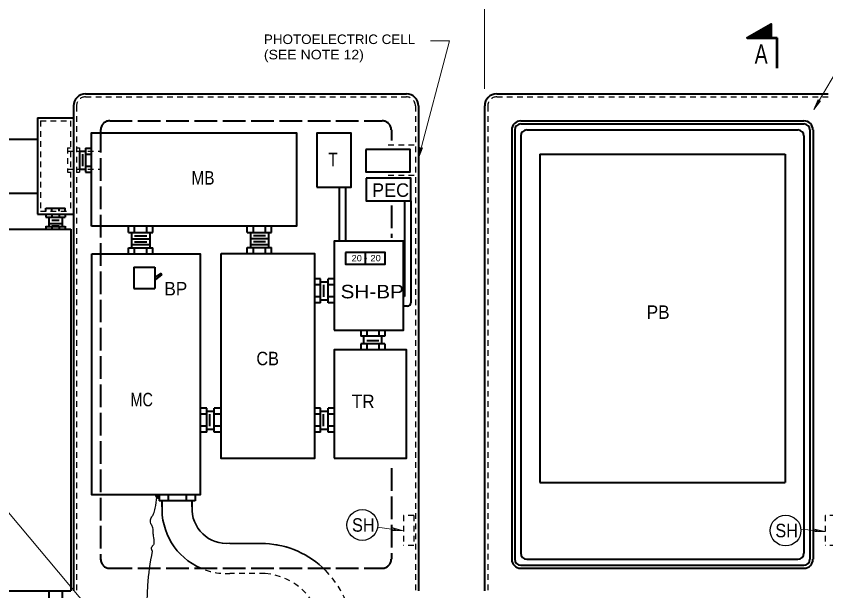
# Model space of a CAD drawing. Extents: x 312583 to 312854, y 144419 to 144597.
# Drawn here: x 312632.5 to 312696.9, y 144527.3 to 144573 of the extents above; entities that cross this region are included whole.
import ezdxf
from ezdxf.enums import TextEntityAlignment as Align

# ---------------------------------------------------------------- set-up
doc = ezdxf.new("R2010")
doc.units = 0
doc.header["$LTSCALE"] = 0.3
doc.header["$PDMODE"] = 32
doc.header["$PDSIZE"] = 0.15
doc.linetypes.add('LONG_DASHED', pattern=[7.5, 6, -1.5])
doc.linetypes.add('SHORT_DASHED', pattern=[2.7, 1.5, -1.2])
doc.layers.add('1', color=7, linetype='Continuous', lineweight=25)
doc.layers.add('2', color=7, linetype='Continuous', lineweight=13)

msp = doc.modelspace()

# ---------------------------------------------------------------- linework, layer by layer
at = {"layer": '1', "lineweight": 35}
for p, q in [((312691.9578, 144571.2646), (312691.6281, 144571.8396)), ((312691.9808, 144571.2646), (312691.6511, 144571.8473)), ((312692.0115, 144571.2646), (312691.6741, 144571.8626)), ((312692.0421, 144571.2646), (312691.6895, 144571.8703)), ((312692.0728, 144571.2646), (312691.7125, 144571.8856)), ((312692.0958, 144571.2646), (312691.7355, 144571.8933)), ((312692.1188, 144571.2646), (312691.7508, 144571.9086)), ((312692.1495, 144571.2723), (312691.7738, 144571.9163)), ((312692.1801, 144571.2646), (312691.7968, 144571.9316)), ((312692.2031, 144571.2646), (312691.8121, 144571.9393)), ((312692.2338, 144571.2646), (312691.8351, 144571.9546)), ((312692.2645, 144571.2646), (312691.8581, 144571.97)), ((312692.2875, 144571.2646), (312691.8811, 144571.9776)), ((312692.3181, 144571.2646), (312691.8965, 144571.993)), ((312692.3488, 144571.2646), (312691.9195, 144572.0083)), ((312692.3718, 144571.2723), (312691.9425, 144572.016)), ((312692.4025, 144571.2723), (312691.9578, 144572.0313)), ((312692.4255, 144571.2646), (312691.9808, 144572.039)), ((312692.4561, 144571.2646), (312692.0038, 144572.0543)), ((312692.4791, 144571.2646), (312692.0191, 144572.062)), ((312692.5098, 144571.2646), (312692.0421, 144572.0773)), ((312692.5405, 144571.2646), (312692.0651, 144572.085)), ((312692.5558, 144571.2876), (312692.0805, 144572.1003)), ((312692.5558, 144571.3413), (312692.1111, 144572.108)), ((312692.5558, 144571.3796), (312692.1265, 144572.1233)), ((312692.5558, 144571.4333), (312692.1495, 144572.131)), ((312692.5558, 144571.4793), (312692.1725, 144572.1463)), ((312692.5558, 144571.5253), (312692.1878, 144572.1616)), ((312692.5558, 144571.5713), (312692.2108, 144572.1693)), ((312692.5558, 144571.625), (312692.2338, 144572.1846)), ((312692.5558, 144571.671), (312692.2491, 144572.2)), ((312692.5558, 144571.717), (312692.2721, 144572.2076)), ((312692.5558, 144571.7706), (312692.2875, 144572.223)), ((312692.5558, 144571.8166), (312692.3105, 144572.2306)), ((312692.5558, 144571.8626), (312692.3335, 144572.246)), ((312692.5558, 144571.9163), (312692.3488, 144572.2536)), ((312692.5558, 144571.9623), (312692.3795, 144572.269)), ((312692.5558, 144572.0083), (312692.3948, 144572.2766)), ((312692.5558, 144572.0543), (312692.4178, 144572.292)), ((312692.5558, 144572.108), (312692.4408, 144572.2996)), ((312692.5558, 144572.1463), (312692.4561, 144572.315)), ((312692.5558, 144572.2), (312692.4791, 144572.3226)), ((312692.5558, 144572.246), (312692.5021, 144572.338)), ((312692.5558, 144572.2996), (312692.5175, 144572.3533)), ((312692.5558, 144572.3456), (312692.5405, 144572.361)), ((312690.6545, 144571.2646), (312690.6545, 144571.28)), ((312690.6851, 144571.2646), (312690.6775, 144571.2876)), ((312690.7158, 144571.2646), (312690.6928, 144571.303)), ((312690.7388, 144571.2646), (312690.7158, 144571.3106)), ((312690.7695, 144571.2646), (312690.7388, 144571.326)), ((312690.7925, 144571.2646), (312690.7541, 144571.3336)), ((312690.8231, 144571.2646), (312690.7771, 144571.349)), ((312690.8538, 144571.2646), (312690.8001, 144571.3566)), ((312690.8845, 144571.2646), (312690.8155, 144571.372)), ((312690.9075, 144571.2646), (312690.8385, 144571.3796)), ((312690.9305, 144571.2646), (312690.8615, 144571.395)), ((312690.9611, 144571.2646), (312690.8845, 144571.4026)), ((312690.9841, 144571.2646), (312690.8998, 144571.418)), ((312691.0148, 144571.2646), (312690.9228, 144571.4333)), ((312691.0455, 144571.2646), (312690.9458, 144571.441)), ((312691.0761, 144571.2646), (312690.9611, 144571.4563)), ((312691.0991, 144571.2646), (312690.9841, 144571.4716)), ((312691.1298, 144571.2646), (312691.0071, 144571.4793)), ((312691.1528, 144571.2646), (312691.0225, 144571.4946)), ((312691.1835, 144571.2646), (312691.0455, 144571.5023)), ((312691.2141, 144571.2646), (312691.0685, 144571.5176)), ((312691.2371, 144571.2646), (312691.0838, 144571.5253)), ((312691.2678, 144571.2646), (312691.1145, 144571.5406)), ((312691.2908, 144571.2646), (312691.1298, 144571.5483)), ((312691.3215, 144571.2646), (312691.1528, 144571.5636)), ((312691.3521, 144571.2646), (312691.1758, 144571.5713)), ((312691.3751, 144571.2646), (312691.1911, 144571.5866)), ((312691.4058, 144571.2646), (312691.2141, 144571.5943)), ((312691.4288, 144571.2646), (312691.2371, 144571.6096)), ((312691.4595, 144571.2646), (312691.2525, 144571.625)), ((312691.4825, 144571.2646), (312691.2755, 144571.6326)), ((312691.5131, 144571.2646), (312691.2985, 144571.648)), ((312691.5438, 144571.2646), (312691.3138, 144571.6633)), ((312691.5745, 144571.2646), (312691.3368, 144571.671)), ((312691.5975, 144571.2646), (312691.3598, 144571.6863)), ((312691.6205, 144571.2646), (312691.3828, 144571.694)), ((312691.6511, 144571.2646), (312691.3981, 144571.7093)), ((312691.6818, 144571.2646), (312691.4211, 144571.717)), ((312691.7048, 144571.2646), (312691.4441, 144571.7323)), ((312691.7355, 144571.2646), (312691.4595, 144571.74)), ((312691.7661, 144571.2646), (312691.4825, 144571.7553)), ((312691.7891, 144571.2646), (312691.5055, 144571.763)), ((312691.8198, 144571.2646), (312691.5208, 144571.7783)), ((312691.8505, 144571.2646), (312691.5438, 144571.786)), ((312691.8735, 144571.2646), (312691.5668, 144571.8013)), ((312691.9041, 144571.2723), (312691.5821, 144571.8166)), ((312691.9271, 144571.2646), (312691.6128, 144571.8243))]:
    msp.add_line(p, q, dxfattribs=at)
at = {"layer": '1', "lineweight": 53}
for p in [(312692.5558, 144571.2646), (312693.0311, 144568.8726)]:
    msp.add_line(p, (312693.0311, 144571.2646), dxfattribs=at)
at = {"layer": '1', "lineweight": 40}
for p, q in [((312638.0151, 144566.8256), (312663.5298, 144566.8256)), ((312670.7135, 144566.8256), (312697.0715, 144566.8256)), ((312637.0568, 144565.8673), (312637.0568, 144527.2963)), ((312664.4881, 144565.8673), (312664.4881, 144527.2963)), ((312669.7551, 144565.8673), (312669.7551, 144527.2963)), ((312634.1818, 144564.909), (312637.0568, 144564.909)), ((312634.1818, 144564.909), (312634.1818, 144557.2423)), ((312672.6301, 144564.6713), (312695.1548, 144564.6713)), ((312672.6301, 144564.4336), (312695.1548, 144564.4336)), ((312671.9171, 144563.9506), (312671.9171, 144529.811)), ((312672.1548, 144563.9506), (312672.1548, 144529.811)), ((312672.6301, 144563.4753), (312672.6301, 144530.2863)), ((312673.1131, 144563.9506), (312694.6718, 144563.9506)), ((312695.1548, 144563.4753), (312695.1548, 144530.2863)), ((312695.6301, 144563.9506), (312695.6301, 144529.811)), ((312695.8755, 144563.9506), (312695.8755, 144529.811)), ((312631.3068, 144563.23), (312634.1818, 144563.23)), ((312637.5245, 144562.264), (312637.5245, 144560.8303)), ((312637.5245, 144562.264), (312637.9998, 144562.264)), ((312637.9998, 144562.5093), (312637.9998, 144560.5926)), ((312637.9998, 144562.5093), (312638.4828, 144562.5093)), ((312637.7621, 144562.0263), (312637.7621, 144561.068)), ((312637.9998, 144562.0263), (312638.4828, 144562.0263)), ((312674.1328, 144562.034), (312674.1328, 144535.9213)), ((312674.1328, 144562.034), (312693.6598, 144562.034)), ((312693.6598, 144562.034), (312693.6598, 144535.9213)), ((312637.9998, 144561.068), (312638.4828, 144561.068)), ((312637.5245, 144560.8303), (312637.9998, 144560.8303)), ((312637.9998, 144560.5926), (312638.4828, 144560.5926)), ((312631.3068, 144558.9213), (312634.1818, 144558.9213)), ((312634.8411, 144557.48), (312634.8411, 144557.7253)), ((312634.8411, 144557.7253), (312636.3975, 144557.7253)), ((312635.3165, 144557.48), (312635.3165, 144557.7253)), ((312635.9221, 144557.48), (312635.9221, 144557.7253)), ((312636.3975, 144557.48), (312636.3975, 144557.7253)), ((312634.1818, 144557.2423), (312637.0568, 144557.2423)), ((312634.8411, 144557.2423), (312634.8411, 144557.0046)), ((312635.3165, 144557.2423), (312635.3165, 144557.0046)), ((312635.9221, 144557.2423), (312635.9221, 144557.0046)), ((312636.3975, 144557.2423), (312636.3975, 144557.0046)), ((312634.8411, 144557.0046), (312636.3975, 144557.0046)), ((312635.0788, 144557.0046), (312635.0788, 144556.284)), ((312635.0788, 144556.5216), (312636.1598, 144556.5216)), ((312635.3165, 144556.767), (312635.9221, 144556.767)), ((312636.1598, 144557.0046), (312636.1598, 144556.284)), ((312631.3068, 144556.0616), (312636.8345, 144556.0616)), ((312634.8411, 144556.2993), (312634.8411, 144556.0616)), ((312634.8411, 144556.284), (312636.3975, 144556.284)), ((312634.8411, 144556.0616), (312636.3975, 144556.0616)), ((312635.3165, 144556.33), (312635.9221, 144556.33)), ((312635.3165, 144556.2993), (312635.3165, 144556.0616)), ((312635.9221, 144556.2993), (312635.9221, 144556.0616)), ((312636.3975, 144556.2993), (312636.3975, 144556.0616)), ((312636.8345, 144556.0616), (312636.8345, 144527.2963)), ((312641.4345, 144555.7856), (312641.4345, 144556.261)), ((312641.4345, 144555.7856), (312643.3511, 144555.7856)), ((312641.6721, 144555.7856), (312641.6721, 144554.582)), ((312641.9175, 144555.7856), (312641.9175, 144556.261)), ((312642.8758, 144555.7856), (312642.8758, 144556.261)), ((312643.1135, 144555.7856), (312643.1135, 144554.582)), ((312643.3511, 144555.7856), (312643.3511, 144556.261)), ((312650.8798, 144555.7933), (312650.8798, 144556.2763)), ((312650.8798, 144555.7933), (312652.7965, 144555.7933)), ((312651.1251, 144555.7933), (312651.1251, 144554.5973)), ((312651.3628, 144555.7933), (312651.3628, 144556.2763)), ((312652.3211, 144555.7933), (312652.3211, 144556.2763)), ((312652.5588, 144555.7933), (312652.5588, 144554.5973)), ((312652.7965, 144555.7933), (312652.7965, 144556.2763)), ((312641.6721, 144555.3026), (312643.1135, 144555.3026)), ((312641.9175, 144555.5403), (312642.8758, 144555.5403)), ((312651.1251, 144555.318), (312652.5588, 144555.318)), ((312651.3628, 144555.5556), (312652.3211, 144555.5556)), ((312641.4345, 144554.582), (312643.3511, 144554.582)), ((312641.4345, 144554.1066), (312641.4345, 144554.582)), ((312641.6721, 144554.8273), (312643.1135, 144554.8273)), ((312641.9175, 144555.065), (312642.8758, 144555.065)), ((312641.9175, 144554.1066), (312641.9175, 144554.582)), ((312642.8758, 144554.1066), (312642.8758, 144554.582)), ((312643.3511, 144554.1066), (312643.3511, 144554.582)), ((312650.8798, 144554.5973), (312652.7965, 144554.5973)), ((312650.8798, 144554.122), (312650.8798, 144554.5973)), ((312651.1251, 144554.835), (312652.5588, 144554.835)), ((312651.3628, 144555.0803), (312652.3211, 144555.0803)), ((312651.3628, 144554.122), (312651.3628, 144554.5973)), ((312652.3211, 144554.122), (312652.3211, 144554.5973)), ((312652.7965, 144554.122), (312652.7965, 144554.5973)), ((312641.8408, 144553.0256), (312641.8408, 144551.3466)), ((312641.8408, 144553.0256), (312643.5198, 144553.0256)), ((312643.5198, 144553.0256), (312643.5198, 144551.3466)), ((312656.7065, 144552.1133), (312656.2311, 144552.1133)), ((312656.7065, 144550.1966), (312656.7065, 144552.1133)), ((312656.7065, 144551.8756), (312657.3121, 144551.8756)), ((312657.3121, 144550.1966), (312657.3121, 144552.1133)), ((312657.7875, 144552.1133), (312657.3121, 144552.1133)), ((312641.8408, 144551.3466), (312643.5198, 144551.3466)), ((312656.7065, 144551.638), (312656.2311, 144551.638)), ((312656.9518, 144550.6796), (312656.9518, 144551.638)), ((312657.7875, 144551.638), (312657.3121, 144551.638)), ((312656.7065, 144550.6796), (312656.2311, 144550.6796)), ((312657.7875, 144550.6796), (312657.3121, 144550.6796)), ((312656.7065, 144550.1966), (312656.2311, 144550.1966)), ((312656.7065, 144550.4343), (312657.3121, 144550.4343)), ((312657.7875, 144550.1966), (312657.3121, 144550.1966)), ((312659.9111, 144548.0116), (312659.9111, 144547.5363)), ((312660.3941, 144548.0116), (312660.3941, 144547.5363)), ((312661.3525, 144548.0116), (312661.3525, 144547.5363)), ((312661.8278, 144548.0116), (312661.8278, 144547.5363)), ((312661.8278, 144547.5363), (312659.9111, 144547.5363)), ((312660.1565, 144546.9383), (312660.1565, 144547.5363)), ((312661.5901, 144546.9383), (312661.5901, 144547.5363)), ((312661.8278, 144546.9383), (312659.9111, 144546.9383)), ((312659.9111, 144546.9383), (312659.9111, 144546.4553)), ((312661.3525, 144547.176), (312660.3941, 144547.176)), ((312660.3941, 144546.9383), (312660.3941, 144546.4553)), ((312661.3525, 144546.9383), (312661.3525, 144546.4553)), ((312661.8278, 144546.9383), (312661.8278, 144546.4553)), ((312647.6521, 144541.8246), (312647.1691, 144541.8246)), ((312647.6521, 144539.908), (312647.6521, 144541.8246)), ((312647.6521, 144541.587), (312648.2501, 144541.587)), ((312648.2501, 144539.908), (312648.2501, 144541.8246)), ((312648.7255, 144541.8246), (312648.2501, 144541.8246)), ((312656.6988, 144541.8246), (312656.2235, 144541.8246)), ((312656.6988, 144539.908), (312656.6988, 144541.8246)), ((312656.6988, 144541.587), (312657.2968, 144541.587)), ((312657.2968, 144539.908), (312657.2968, 144541.8246)), ((312657.7798, 144541.8246), (312657.2968, 144541.8246)), ((312647.6521, 144541.3416), (312647.1691, 144541.3416)), ((312647.8898, 144540.3833), (312647.8898, 144541.3416)), ((312648.7255, 144541.3416), (312648.2501, 144541.3416)), ((312656.6988, 144541.3416), (312656.2235, 144541.3416)), ((312656.9365, 144540.3833), (312656.9365, 144541.3416)), ((312657.7798, 144541.3416), (312657.2968, 144541.3416)), ((312647.6521, 144540.3833), (312647.1691, 144540.3833)), ((312648.7255, 144540.3833), (312648.2501, 144540.3833)), ((312656.6988, 144540.3833), (312656.2235, 144540.3833)), ((312657.7798, 144540.3833), (312657.2968, 144540.3833)), ((312647.6521, 144539.908), (312647.1691, 144539.908)), ((312647.6521, 144540.1456), (312648.2501, 144540.1456)), ((312648.7255, 144539.908), (312648.2501, 144539.908)), ((312656.6988, 144539.908), (312656.2235, 144539.908)), ((312656.6988, 144540.1456), (312657.2968, 144540.1456)), ((312657.7798, 144539.908), (312657.2968, 144539.908)), ((312674.1328, 144535.9213), (312693.6598, 144535.9213)), ((312643.8571, 144534.94), (312643.8571, 144534.457)), ((312644.5778, 144534.94), (312644.5778, 144534.457)), ((312644.5778, 144534.526), (312644.5778, 144534.457)), ((312646.0115, 144534.94), (312646.0115, 144534.457)), ((312646.0115, 144534.526), (312646.0115, 144534.457)), ((312646.7321, 144534.94), (312646.7321, 144534.457)), ((312646.7321, 144534.526), (312646.7321, 144534.457)), ((312646.7321, 144534.457), (312643.8571, 144534.457)), ((312644.0948, 144533.9816), (312644.0948, 144534.457)), ((312646.4945, 144533.9816), (312646.4945, 144534.457)), ((312672.6301, 144529.328), (312695.1548, 144529.328)), ((312673.1131, 144529.811), (312694.6718, 144529.811)), ((312672.6301, 144529.0903), (312695.1548, 144529.0903)), ((312631.3068, 144527.2963), (312636.8345, 144527.2963)), ((312635.0788, 144527.2963), (312635.0788, 144520.8256)), ((312636.1598, 144527.2963), (312636.1598, 144520.8256))]:
    msp.add_line(p, q, dxfattribs=at)
at = {"layer": '1', "linetype": 'SHORT_DASHED'}
for p, q in [((312638.0151, 144566.588), (312663.5298, 144566.588)), ((312670.7135, 144566.588), (312697.0715, 144566.588)), ((312637.2945, 144565.8673), (312637.2945, 144527.2963)), ((312664.2505, 144565.8673), (312664.2505, 144527.2963)), ((312670.0005, 144565.8673), (312670.0005, 144527.2963)), ((312634.4195, 144564.6713), (312636.8191, 144564.6713)), ((312636.8191, 144564.6713), (312636.8191, 144557.48)), ((312636.5738, 144562.517), (312636.5738, 144560.6003)), ((312636.5738, 144562.517), (312636.8191, 144562.517)), ((312636.5738, 144562.2716), (312639.2111, 144562.2716)), ((312636.5738, 144562.2716), (312637.5398, 144562.2716)), ((312637.2945, 144562.517), (312637.5321, 144562.517)), ((312637.5321, 144562.517), (312637.5321, 144560.6003)), ((312662.0885, 144562.7546), (312664.2505, 144562.7546)), ((312636.5738, 144560.838), (312639.2111, 144560.838)), ((312636.5738, 144560.838), (312637.6165, 144560.838)), ((312636.5738, 144560.6003), (312636.8191, 144560.6003)), ((312637.2945, 144560.6003), (312637.5321, 144560.6003)), ((312662.0885, 144560.355), (312664.2505, 144560.355)), ((312664.1278, 144533.284), (312663.2921, 144533.284)), ((312663.2921, 144533.284), (312663.2921, 144530.892)), ((312664.1278, 144533.284), (312664.1278, 144530.892)), ((312697.6695, 144533.284), (312696.8338, 144533.284)), ((312696.8338, 144533.284), (312696.8338, 144530.892)), ((312664.1278, 144530.892), (312663.2921, 144530.892)), ((312697.6695, 144530.892), (312696.8338, 144530.892))]:
    msp.add_line(p, q, dxfattribs=at)
at = {"layer": '1', "linetype": 'LONG_DASHED', "lineweight": 40}
for p, q in [((312639.9318, 144564.6713), (312661.6131, 144564.6713)), ((312639.2111, 144563.9506), (312639.2111, 144529.811)), ((312662.3338, 144563.9506), (312662.3338, 144563.115)), ((312662.3338, 144557.9323), (312662.3338, 144555.3716)), ((312662.3338, 144537.0483), (312662.3338, 144529.811)), ((312639.9318, 144529.0903), (312661.6131, 144529.0903))]:
    msp.add_line(p, q, dxfattribs=at)
at = {"layer": '1', "lineweight": 13}
msp.add_line((312639.8398, 144524.0303), (312628.9915, 144536.9563), dxfattribs=at)
at = {"layer": '1', "lineweight": 53}
msp.add_lwpolyline([(312692.5558, 144571.2646), (312692.5558, 144572.3763), (312690.6391, 144571.2646)], close=True, dxfattribs=at)
at = {"layer": '1', "linetype": 'SHORT_DASHED'}
msp.add_lwpolyline([(312634.4195, 144564.6713), (312634.4195, 144557.48), (312636.8191, 144557.48)], dxfattribs=at)
at = {"layer": '1', "lineweight": 40}
msp.add_lwpolyline([(312643.5658, 144552.2513), (312644.0105, 144552.535), (312644.0488, 144552.42), (312643.5658, 144552.0596)], dxfattribs=at)
at = {"layer": '1', "lineweight": 35}
msp.add_lwpolyline([(312643.6425, 144534.9323), (312643.6118, 144534.871), (312643.6425, 144534.7483), (312643.6885, 144534.7176), (312643.7728, 144534.6716), (312643.8495, 144534.6716), (312643.8571, 144534.94), (312643.6578, 144534.9246), (312643.6271, 144534.8786), (312643.6501, 144534.7636), (312643.7728, 144534.687), (312643.8341, 144534.6946), (312643.8495, 144534.917), (312643.6808, 144534.917), (312643.6501, 144534.8863), (312643.6501, 144534.779), (312643.7728, 144534.7023), (312643.8265, 144534.71), (312643.8265, 144534.9016), (312643.6885, 144534.9016), (312643.6731, 144534.7866), (312643.7728, 144534.7176), (312643.8188, 144534.7176), (312643.8111, 144534.8786), (312643.7038, 144534.8863), (312643.6885, 144534.7866), (312643.7651, 144534.7253), (312643.8035, 144534.7253), (312643.7958, 144534.871), (312643.7345, 144534.8786), (312643.6961, 144534.802), (312643.7651, 144534.7406), (312643.7881, 144534.8326), (312643.7651, 144534.871), (312643.7421, 144534.8326), (312643.7575, 144534.802), (312643.7728, 144534.8173), (312643.7345, 144534.8326), (312643.7345, 144534.7943), (312643.7651, 144534.756), (312643.7881, 144534.7483), (312643.6731, 144534.8786)], dxfattribs=at)
at = {"layer": '1', "lineweight": 40}
for centre, radius, start, end in [((312638.0142, 144565.8673), 0.9583, 90, 180), ((312663.5288, 144565.8673), 0.9583, 0, 90), ((312670.7163, 144565.8673), 0.9583, 90, 180), ((312672.633, 144563.9506), 0.7188, 90, 180), ((312672.633, 144563.9506), 0.4792, 90, 180), ((312695.1538, 144563.9506), 0.7188, 0, 90), ((312695.1538, 144563.9506), 0.4792, 0, 90), ((312673.1122, 144563.4715), 0.4792, 90, 180), ((312694.6747, 144563.4715), 0.4792, 0, 90), ((312673.1122, 144530.2892), 0.4792, 180, 270), ((312694.6747, 144530.2892), 0.4792, 270, 0), ((312672.633, 144529.81), 0.7188, 180, 270), ((312672.633, 144529.81), 0.4792, 180, 270), ((312695.1538, 144529.81), 0.7188, 270, 0), ((312695.1538, 144529.81), 0.4792, 270, 0)]:
    msp.add_arc(centre, radius, start, end, dxfattribs=at)
at = {"layer": '1', "linetype": 'SHORT_DASHED'}
for centre, radius, start, end in [((312638.0142, 144565.8673), 0.7188, 90, 180), ((312663.5288, 144565.8673), 0.7188, 0, 90), ((312670.7163, 144565.8673), 0.7188, 90, 180), ((312651.9456, 144523.7862), 7.2781, 3.16058, 87.12347), ((312651.9456, 144523.7862), 4.8914, 4.70558, 85.88958)]:
    msp.add_arc(centre, radius, start, end, dxfattribs=at)
at = {"layer": '1', "linetype": 'LONG_DASHED', "lineweight": 40}
for centre, start, end in [((312639.9308, 144563.9506), 90, 180), ((312661.6122, 144563.9506), 0, 90), ((312639.9308, 144529.81), 180, 270), ((312661.6122, 144529.81), 270, 0)]:
    msp.add_arc(centre, 0.7188, start, end, dxfattribs=at)
at = {"layer": '1', "lineweight": 35}
msp.add_arc((312651.9456, 144523.7862), 7.2781, 45.10063, 87.12347, dxfattribs=at)
at = {"layer": '1'}
msp.add_spline([(312637.3941, 144522.2593), (312638.0228, 144522.382), (312638.7205, 144522.6503), (312639.1728, 144523.164), (312639.6558, 144523.946), (312640.3151, 144524.245), (312641.2198, 144524.5516), (312642.3315, 144525.1496), (312642.8145, 144526.085), (312642.9678, 144527.718), (312643.3358, 144530.4396)], degree=3, dxfattribs=at)
at = {"layer": '2'}
for p, q in [((312669.7551, 144567.209), (312669.7551, 144574.408)), ((312664.4881, 144561.712), (312666.9645, 144571.0423)), ((312666.9645, 144571.0423), (312665.4541, 144571.0423)), ((312698.5322, 144569.9951), (312695.9445, 144565.5683)), ((312695.9445, 144565.5683), (312696.2847, 144566.3724)), ((312695.9445, 144565.5683), (312696.4714, 144566.2708)), ((312696.2847, 144566.3724), (312696.2393, 144566.083)), ((312696.4714, 144566.2708), (312696.2393, 144566.083)), ((312664.4881, 144561.712), (312664.6031, 144562.5783)), ((312664.4881, 144561.712), (312664.8101, 144562.5246)), ((312664.6031, 144562.5783), (312664.6415, 144562.287)), ((312664.8101, 144562.5246), (312664.6415, 144562.287)), ((312661.8355, 144554.2293), (312661.8355, 144553.3553)), ((312661.2375, 144532.364), (312663.2921, 144532.0726)), ((312662.4181, 144532.088), (312662.7018, 144532.1493)), ((312663.2921, 144532.0726), (312662.4181, 144532.088)), ((312662.4488, 144532.295), (312662.7018, 144532.1493)), ((312663.2921, 144532.0726), (312662.4488, 144532.295)), ((312694.9095, 144532.203), (312696.8338, 144532.019)), ((312695.9598, 144531.996), (312696.2435, 144532.0726)), ((312696.8338, 144532.019), (312695.9598, 144531.996)), ((312695.9828, 144532.2106), (312696.2435, 144532.0726)), ((312696.8338, 144532.019), (312695.9828, 144532.2106))]:
    msp.add_line(p, q, dxfattribs=at)
at = {"layer": '2', "lineweight": 40}
for p, q in [((312658.1785, 144559.3966), (312658.1785, 144555.0956)), ((312658.6921, 144559.3966), (312658.6921, 144555.0956)), ((312663.3688, 144558.3156), (312663.3688, 144550.695)), ((312663.8825, 144558.3156), (312663.8825, 144550.1966)), ((312660.2715, 144553.2863), (312660.2715, 144554.191)), ((312663.3688, 144550.695), (312663.2921, 144550.695)), ((312663.6218, 144549.936), (312663.2921, 144549.936))]:
    msp.add_line(p, q, dxfattribs=at)
at = {"layer": '2', "lineweight": 35}
msp.add_line((312652.3135, 144531.053), (312649.4921, 144531.053), dxfattribs=at)
at = {"layer": '2', "linetype": 'SHORT_DASHED', "lineweight": 25}
msp.add_line((312652.2981, 144528.6686), (312649.4768, 144528.6686), dxfattribs=at)
at = {"layer": '2', "lineweight": 40}
for points in [[(312638.4905, 144556.2916), (312638.4905, 144563.713), (312654.7821, 144563.713), (312654.7821, 144556.2916)], [(312656.4075, 144559.3966), (312659.1445, 144559.3966), (312659.1445, 144563.7053), (312656.4075, 144563.7053)], [(312660.2945, 144562.402), (312660.2945, 144560.608), (312663.8365, 144560.608), (312663.8365, 144562.402)], [(312660.3405, 144560.1096), (312660.3405, 144558.3156), (312663.8825, 144558.3156), (312663.8825, 144560.1096)], [(312657.7875, 144548.027), (312663.2921, 144548.027), (312663.2921, 144555.0956), (312657.7875, 144555.0956)], [(312638.5058, 144554.1066), (312647.1308, 144554.1066), (312647.1308, 144534.94), (312638.5058, 144534.94)], [(312648.7945, 144554.1143), (312656.2235, 144554.1143), (312656.2235, 144537.8226), (312648.7945, 144537.8226)], [(312658.6998, 144554.191), (312658.6998, 144553.2863), (312661.8431, 144553.2863), (312661.8431, 144554.191)], [(312657.7875, 144537.8456), (312663.5375, 144537.8456), (312663.5375, 144546.4706), (312657.7875, 144546.4706)]]:
    msp.add_lwpolyline(points, close=True, dxfattribs=at)
at = {"layer": '2', "lineweight": 25}
for centre in [(312660.0271, 144532.5307), (312693.6953, 144532.0889)]:
    msp.add_circle(centre, 1.2209, dxfattribs=at)
at = {"layer": '2', "lineweight": 40}
msp.add_arc((312663.6252, 144550.1947), 0.2583, 269.8939, 0, dxfattribs=at)
at = {"layer": '2', "lineweight": 35}
for radius, end in [(5.1349, 246.60841), (2.7408, 275.55762)]:
    msp.add_arc((312649.2286, 144533.8029), radius, 176.64221, end, dxfattribs=at)
at = {"layer": '2', "linetype": 'SHORT_DASHED', "lineweight": 25}
msp.add_arc((312649.2286, 144533.8029), 5.1349, 241.7165, 272.79738, dxfattribs=at)
at = {"layer": '2', "lineweight": 25}
for points in [[(312643.3818, 144531.8043), (312643.3588, 144532.3103), (312643.2438, 144532.571), (312643.1825, 144532.7473), (312643.2055, 144533.008), (312643.2898, 144533.1843), (312643.4201, 144533.4066), (312643.5581, 144533.8666), (312643.6885, 144534.7483)], [(312643.3818, 144531.8043), (312643.4431, 144531.2293), (312643.4048, 144530.9456), (312643.2438, 144530.7233), (312643.3358, 144530.4396)]]:
    msp.add_spline(points, degree=3, dxfattribs=at)
at = {"layer": '2'}
msp.add_point((312660.2715, 144553.7386), dxfattribs=at)

# ---------------------------------------------------------------- texts
at = {"layer": '1', "width": 0.75}
msp.add_text('A', height=1.533, dxfattribs=at).set_placement((312691.7508, 144569.233), align=Align.CENTER)
at = {"layer": '2'}
for s, width, p in [('PHOTOELECTRIC CELL', 1.05, (312652.1966, 144570.7837)), ('(SEE NOTE 12)', 1.1, (312652.1966, 144569.5637))]:
    msp.add_text(s, height=0.76, dxfattribs=dict(at, width=width)).set_placement(p)
for s, height, width, p in [('T', 1.072, 0.85, (312657.6916, 144561.0603)), ('MB', 1.072, 0.85, (312647.3531, 144559.6036)), ('20', 0.4983, 1.1, (312659.5815, 144553.501)), ('20', 0.4983, 1.1, (312661.0841, 144553.5086)), ('BP', 1.072, 0.95, (312645.1911, 144550.787)), ('SH-BP', 1.072, 1.15, (312660.8158, 144550.557)), ('PB', 1.072, 0.95, (312683.5551, 144548.924)), ('CB', 1.072, 0.9, (312652.4974, 144545.2363)), ('MC', 1.072, 0.8, (312642.4771, 144541.9703)), ('TR', 1.072, 0.95, (312660.0951, 144541.8246)), ('SH', 1.072, 0.9, (312660.1028, 144531.996)), ('SH', 1.072, 0.9, (312693.7748, 144531.5513))]:
    msp.add_text(s, height=height, dxfattribs=dict(at, width=width)).set_placement(p, align=Align.CENTER)
msp.add_text('PEC', height=1.072, dxfattribs=at).set_placement((312662.2724, 144558.63), align=Align.CENTER)

doc.saveas('drawing.dxf')
